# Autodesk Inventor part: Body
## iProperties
Created: 2002-01
Part Number: Body
Document SubType Name: Modeling
Designer: ***
Control State: 0
Master: False
Checked Out: False
Shininess: 20.0
Length Units: 11269
Angle Units: 11279
Time Units: 11290
Mass Units: 11283
Length Display Precision: 3
Angle Display Precision: 2
Density: 0.0
Volumn: 0.0
Area: 0.0
PropertySet Name: Model Information
Author: ***
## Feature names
1. Extrusion1
2. Extrusion2
3. Circular Pattern1
4. Mirror1
5. Extrusion3
6. Extrusion4
7. Hole1
8. Hole2
9. Circular Pattern2
